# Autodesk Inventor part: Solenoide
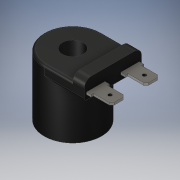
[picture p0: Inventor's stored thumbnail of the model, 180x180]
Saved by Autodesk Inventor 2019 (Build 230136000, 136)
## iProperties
Created: 2019-04
Part Number: Solenoide
Material: Generic
Document SubType Name: Modeling
Designer: Plo
Density: 1 g/cm^3
Appearance: Glossy - Black
Author: Plo
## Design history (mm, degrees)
sketch "Sketch1"
  geometry: C1 r 12.5 at (0, 0); 1 further point
  constraints: 1 centre point, 1 coincident
  dimensions: "d0" = 25 diameter of C1
extrude "Extrusion1" new body sketch "Sketch1" distance "d1" = 27; taper "d2" = 0 deg
workplane "Work Plane1"
sketch "Sketch2"
  geometry: L1 (27, -12.5)-(27, 12.5) reference; L2 (27, 12.5)-(27, -12.5); L3 (27, -12.5)-(22, -12.5); L4 (0, -12.5)-(27, -12.5) reference; L5 (22, -12.5)-(22, 12.5); L6 (22, 12.5)-(27, 12.5); L7 (0, 12.5)-(27, 12.5) reference; 1 further point
  constraints: 8 end point, 2 collinear, 1 point on line, 1 vertical
  dimensions: "d3" = 5 distance of L1.start L3.end
extrude "Extrusion2" join sketch "Sketch2" stored distance "d4" = 22; taper "d5" = 0 deg
sketch "Sketch3"
  geometry: L1 (-12.5, 22)-(-12.5, 27) reference; L2 (-12.5, 22)-(-12.5, 30); L3 (-12.5, 30)-(12.5, 30); L4 (12.5, 22)-(12.5, 27) reference; L5 (12.5, 30)-(12.5, 22); L6 (-12.5, 22)-(0, 22) reference; L7 (12.5, 22)-(-12.5, 22); 1 further point
  constraints: 8 end point, 2 collinear, 1 perpendicular, 1 vertical
  dimensions: "d6" = 8 distance of L1.start L2.end
extrude "Extrusion3" join sketch "Sketch3" distance "d7" = 5; taper "d8" = 0 deg
sketch "Sketch4"
  geometry: L1 (-12.5, 22)-(12.5, 22) reference; L2 (-12.5, 22)-(-12.5, 24); L3 (-12.5, 24)-(-11.5, 24); L4 (-11.5, 24)-(-11.5, 25); L5 (-11.5, 25)-(-3.5, 25); L6 (-3.5, 25)-(-3.5, 24); L7 (-3.5, 24)-(-11.5, 24); 1 further point
  constraints: 12 end point, 3 perpendicular, 1 point on line, 1 vertical
  dimensions: "d9" = 2 distance of L1.start L2.end; "d10" = 1 distance of L2.end L3.end; "d11" = 1 distance of L3.end L4.end; "d12" = 8 distance of L4.end L5.end; "d13" = 1 distance of L5.end L6.end
extrude "Extrusion4" join sketch "Sketch4" distance "d14" = 10; taper "d15" = 0 deg
sketch "Sketch5"
  geometry: L1 (10, 0)-(10, 8) reference; L2 (10, 4)-(6.25, 4); L3 (0, 8)-(10, 8) reference; L4 (10, 8)-(10, 7); L5 (9, 7)-(2, 7); L6 (2, 7)-(2, 8); L7 (0, 8)-(10, 8) reference; L8 (10, 7)-(10, 6); L9 (9, 7)-(10, 6); L10 (9, 1)-(10, 2); L11 (9, 1)-(2, 1); L12 (2, 1)-(2, 0); L13 (0, 0)-(10, 0) reference; L14 (2, 0)-(10, 0); L15 (10, 0)-(10, 2); C1 r 0.75 at (6.25, 4); 1 further point
  constraints: 22 end point, 4 symmetric about line, 3 perpendicular, 3 point on line, 2 horizontal, 1 centre point, 1 coincident, 1 midpoint
extrude "Extrusion5" cut sketch "Sketch5" stored distance "d22" = 10; taper "d23" = 0 deg
mirror "Mirror1"
fillet "Fillet1" dims "d24" = 3, "d25" = 1
sketch "Sketch6"
  geometry: C1 r 4.5 at (0, 0); 1 further point
  constraints: 1 centre point, 1 coincident
  dimensions: "d26" = 9 diameter of C1
extrude "Extrusion6" cut sketch "Sketch6" stored distance "d27" = 10; taper "d28" = 0 deg
body "Solid1"
